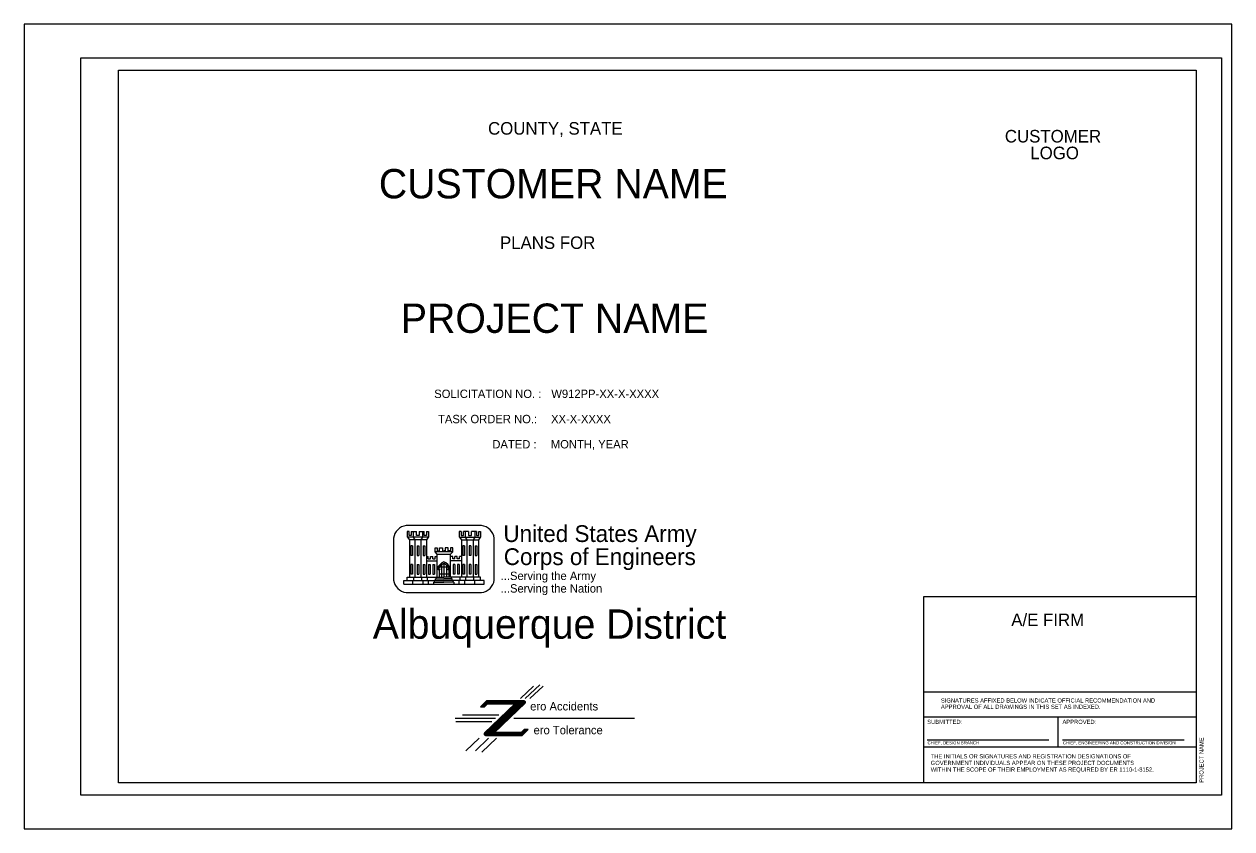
# Model space of a CAD drawing. Extents: x 0 to 288, y 0 to 192.
import ezdxf

# ---------------------------------------------------------------- set-up
doc = ezdxf.new("R2010")
doc.units = 0
for name, color, linetype in [('G-ANNO-SYMB', 7, 'Continuous'), ('G-ANNO-TEXT', 7, 'Continuous'), ('G-ANNO-TTBL', 7, 'Continuous')]:
    doc.layers.add(name, color=color, linetype=linetype)

msp = doc.modelspace()

# ---------------------------------------------------------------- linework, layer by layer
at = {"layer": 'G-ANNO-SYMB'}
for p, q in [((109.09, 72.37), (91.09, 72.37)), ((88.09, 69.37), (88.09, 59.37)), ((112.09, 59.37), (112.09, 69.37)), ((98.94, 61.94), (98.94, 61.94)), ((90.51, 59.27), (91.32, 59.27)), ((91.32, 60.08), (91.86, 60.08)), ((108.86, 60.08), (108.32, 60.08)), ((109.67, 59.27), (108.86, 59.27)), ((91.09, 56.37), (109.09, 56.37)), ((121.47, 34.07), (118.35, 31.08)), ((122.95, 34.4), (119.48, 31.08)), ((123.73, 34.07), (120.61, 31.08)), ((110.28, 30.56), (108.8, 29.15)), ((108.8, 29.15), (109.76, 29.15)), ((108.86, 29.2), (109.82, 29.2)), ((108.95, 29.28), (109.91, 29.28)), ((109.02, 29.36), (109.98, 29.36)), ((109.1, 29.43), (110.06, 29.43)), ((109.19, 29.51), (110.15, 29.51)), ((109.26, 29.59), (110.22, 29.59)), ((109.35, 29.66), (110.3, 29.66)), ((109.43, 29.74), (110.39, 29.74)), ((109.5, 29.82), (110.46, 29.82)), ((109.59, 29.89), (119.37, 29.89)), ((109.67, 29.97), (119.45, 29.97)), ((109.74, 30.05), (119.5, 30.05)), ((109.76, 29.15), (110.48, 29.84)), ((117.05, 29.84), (109.77, 22.89)), ((109.83, 30.12), (119.54, 30.12)), ((109.91, 30.2), (119.54, 30.2)), ((109.99, 30.28), (119.55, 30.28)), ((110.07, 30.36), (119.52, 30.36)), ((110.15, 30.43), (119.48, 30.43)), ((110.23, 30.51), (119.39, 30.51)), ((119.22, 30.56), (110.28, 30.56)), ((110.48, 29.84), (117.05, 29.84)), ((112.18, 23.03), (119.46, 29.98)), ((115.98, 28.82), (118.24, 28.82)), ((116.06, 28.9), (118.32, 28.9)), ((116.15, 28.97), (118.4, 28.97)), ((116.22, 29.05), (118.48, 29.05)), ((116.31, 29.13), (118.56, 29.13)), ((116.39, 29.2), (118.64, 29.2)), ((116.46, 29.28), (118.73, 29.28)), ((116.55, 29.36), (118.8, 29.36)), ((116.63, 29.43), (118.88, 29.43)), ((116.7, 29.51), (118.97, 29.51)), ((116.79, 29.59), (119.04, 29.59)), ((116.87, 29.66), (119.12, 29.66)), ((116.95, 29.74), (119.21, 29.74)), ((117.03, 29.82), (119.28, 29.82)), ((119.22, 30.56), (119.22, 30.56)), ((112.38, 26.36), (102.78, 26.36)), ((113.21, 27.15), (104.57, 27.15)), ((113.01, 25.98), (115.26, 25.98)), ((113.08, 26.05), (115.35, 26.05)), ((113.17, 26.13), (115.43, 26.13)), ((113.25, 26.21), (115.51, 26.21)), ((113.33, 26.28), (115.59, 26.28)), ((113.41, 26.36), (115.67, 26.36)), ((113.49, 26.44), (115.75, 26.44)), ((113.57, 26.52), (115.83, 26.52)), ((113.65, 26.59), (115.91, 26.59)), ((113.74, 26.67), (115.99, 26.67)), ((113.81, 26.75), (116.07, 26.75)), ((113.89, 26.82), (116.15, 26.82)), ((113.98, 26.9), (116.23, 26.9)), ((114.05, 26.98), (116.31, 26.98)), ((114.13, 27.05), (116.39, 27.05)), ((114.22, 27.13), (116.47, 27.13)), ((114.29, 27.21), (116.55, 27.21)), ((114.38, 27.28), (116.63, 27.28)), ((114.46, 27.36), (116.71, 27.36)), ((114.53, 27.44), (116.8, 27.44)), ((114.62, 27.51), (116.87, 27.51)), ((114.7, 27.59), (116.95, 27.59)), ((114.77, 27.67), (117.04, 27.67)), ((114.86, 27.74), (117.11, 27.74)), ((114.94, 27.82), (117.19, 27.82)), ((115.02, 27.9), (117.28, 27.9)), ((115.1, 27.97), (117.35, 27.97)), ((115.18, 28.05), (117.44, 28.05)), ((115.26, 28.13), (117.52, 28.13)), ((115.34, 28.2), (117.59, 28.2)), ((115.42, 28.28), (117.68, 28.28)), ((115.5, 28.36), (117.76, 28.36)), ((115.58, 28.44), (117.83, 28.44)), ((115.67, 28.51), (117.92, 28.51)), ((115.74, 28.59), (118, 28.59)), ((115.82, 28.67), (118.08, 28.67)), ((115.91, 28.74), (118.16, 28.74)), ((116.76, 26.41), (145.56, 26.41)), ((111.56, 25.57), (102.92, 25.57)), ((109.95, 23.06), (112.21, 23.06)), ((110.03, 23.14), (112.3, 23.14)), ((110.12, 23.21), (112.37, 23.21)), ((110.19, 23.29), (112.45, 23.29)), ((110.27, 23.37), (112.54, 23.37)), ((110.36, 23.44), (112.61, 23.44)), ((110.43, 23.52), (112.69, 23.52)), ((110.51, 23.6), (112.78, 23.6)), ((110.6, 23.67), (112.85, 23.67)), ((110.67, 23.75), (112.94, 23.75)), ((110.76, 23.83), (113.02, 23.83)), ((110.84, 23.9), (113.09, 23.9)), ((110.91, 23.98), (113.18, 23.98)), ((111, 24.06), (113.26, 24.06)), ((111.08, 24.13), (113.33, 24.13)), ((111.15, 24.21), (113.42, 24.21)), ((111.24, 24.29), (113.5, 24.29)), ((111.32, 24.36), (113.58, 24.36)), ((111.4, 24.44), (113.66, 24.44)), ((111.48, 24.52), (113.74, 24.52)), ((111.56, 24.6), (113.82, 24.6)), ((111.64, 24.67), (113.9, 24.67)), ((111.72, 24.75), (113.98, 24.75)), ((111.8, 24.83), (114.06, 24.83)), ((111.88, 24.9), (114.14, 24.9)), ((111.96, 24.98), (114.23, 24.98)), ((112.05, 25.06), (114.3, 25.06)), ((112.12, 25.13), (114.38, 25.13)), ((112.2, 25.21), (114.47, 25.21)), ((112.29, 25.29), (114.54, 25.29)), ((112.36, 25.36), (114.62, 25.36)), ((112.44, 25.44), (114.71, 25.44)), ((112.53, 25.52), (114.78, 25.52)), ((112.6, 25.59), (114.87, 25.59)), ((112.69, 25.67), (114.95, 25.67)), ((112.77, 25.75), (115.02, 25.75)), ((112.84, 25.82), (115.11, 25.82)), ((112.93, 25.9), (115.19, 25.9)), ((119.27, 23.72), (118.55, 23.03)), ((118.58, 23.06), (119.54, 23.06)), ((118.66, 23.14), (119.62, 23.14)), ((118.75, 23.21), (119.7, 23.21)), ((118.76, 22.31), (120.23, 23.72)), ((118.82, 23.29), (119.78, 23.29)), ((118.9, 23.37), (119.86, 23.37)), ((118.99, 23.44), (119.95, 23.44)), ((119.06, 23.52), (120.02, 23.52)), ((119.14, 23.6), (120.1, 23.6)), ((119.23, 23.67), (120.19, 23.67)), ((120.23, 23.72), (119.27, 23.72)), ((108.47, 21.64), (105.35, 18.65)), ((107.6, 18.65), (110.72, 21.64)), ((112.63, 21.64), (109.15, 18.33)), ((109.67, 22.6), (119.05, 22.6)), ((109.68, 22.75), (119.22, 22.75)), ((109.68, 22.68), (119.14, 22.68)), ((109.7, 22.52), (118.98, 22.52)), ((109.73, 22.83), (119.3, 22.83)), ((109.74, 22.44), (118.9, 22.44)), ((109.79, 22.91), (119.38, 22.91)), ((109.83, 22.37), (118.81, 22.37)), ((109.87, 22.98), (119.46, 22.98)), ((110.01, 22.31), (118.76, 22.31)), ((118.55, 23.03), (112.18, 23.03))]:
    msp.add_line(p, q, dxfattribs=at)
for points in [[(91.79, 70.94), (91.32, 70.94), (91.32, 69.65), (91.86, 68.97), (91.86, 60.08)], [(96.41, 69.59), (91.37, 69.59)], [(92.33, 70.94), (92.33, 69.99), (91.79, 69.99), (91.79, 70.94)], [(92.33, 70.94), (93.55, 70.94)], [(92.74, 70.94), (92.74, 69.61), (93.14, 68.94), (93.14, 60.08)], [(94.22, 70.94), (94.22, 69.99), (93.55, 69.99), (93.55, 70.94)], [(94.22, 70.94), (95.43, 70.94)], [(95.03, 70.94), (95.03, 69.61), (94.63, 68.94), (94.63, 60.08)], [(95.98, 70.94), (95.98, 69.99), (95.43, 69.99), (95.43, 70.94)], [(95.98, 70.94), (96.45, 70.94), (96.45, 69.65), (95.91, 68.97), (95.91, 60.08)], [(104.21, 70.94), (103.74, 70.94), (103.74, 69.65), (104.27, 68.97), (104.27, 60.08)], [(103.78, 69.59), (108.82, 69.59)], [(104.21, 70.94), (104.21, 69.99), (104.75, 69.99), (104.75, 70.94)], [(105.96, 70.94), (104.75, 70.94)], [(105.15, 70.94), (105.15, 69.61), (105.56, 68.94), (105.56, 60.08)], [(105.96, 70.94), (105.96, 69.99), (106.64, 69.99), (106.64, 70.94)], [(107.85, 70.94), (106.64, 70.94)], [(107.45, 70.94), (107.45, 69.61), (107.04, 68.94), (107.04, 60.08)], [(107.85, 70.94), (107.85, 69.99), (108.39, 69.99), (108.39, 70.94)], [(108.39, 70.94), (108.86, 70.94), (108.86, 69.65), (108.32, 68.97), (108.32, 60.08)], [(95.92, 68.98), (91.85, 68.98)], [(92.6, 67.5), (92.2, 67.5)], [(92.2, 67.5), (92.2, 65.21)], [(92.6, 67.5), (92.6, 65.21)], [(93.69, 67.5), (94.09, 67.5)], [(93.69, 67.5), (93.69, 65.21)], [(94.09, 67.5), (94.09, 65.21)], [(95.17, 67.5), (95.17, 65.21)], [(95.17, 67.5), (95.57, 67.5)], [(95.57, 67.5), (95.57, 65.21)], [(98.47, 60.08), (98.47, 65.55), (98, 66.08), (98, 67.03), (98.47, 67.03)], [(98.47, 67.03), (98.47, 66.35), (99.08, 66.35), (99.08, 67.03)], [(99.08, 67.03), (99.76, 67.03)], [(99.76, 67.03), (99.76, 66.35), (100.16, 66.35)], [(100.43, 67.03), (100.43, 66.35), (100.16, 66.35)], [(101.1, 67.03), (100.43, 67.03)], [(101.71, 67.03), (101.71, 66.35), (101.1, 66.35), (101.1, 67.03)], [(101.71, 60.08), (101.71, 65.55), (102.19, 66.08), (102.19, 67.03), (101.71, 67.03)], [(104.27, 68.98), (108.33, 68.98)], [(105.01, 67.5), (104.61, 67.5)], [(104.61, 67.5), (104.61, 65.21)], [(105.01, 67.5), (105.01, 65.21)], [(106.09, 67.5), (106.09, 65.21)], [(106.49, 67.5), (106.09, 67.5)], [(106.49, 67.5), (106.49, 65.21)], [(107.58, 67.5), (107.58, 65.21)], [(107.58, 67.5), (107.98, 67.5)], [(107.98, 67.5), (107.98, 65.21)], [(92.6, 65.21), (92.2, 65.21)], [(93.69, 65.21), (94.09, 65.21)], [(95.17, 65.21), (95.57, 65.21)], [(95.91, 65), (96.38, 65)], [(95.91, 63.92), (98.47, 63.92)], [(96.38, 64.46), (96.38, 65)], [(96.38, 64.46), (96.92, 64.46)], [(96.92, 65), (97.46, 65)], [(96.92, 64.46), (96.92, 65)], [(97.46, 64.46), (97.46, 65)], [(97.46, 64.46), (98, 64.46)], [(98, 65), (98.47, 65)], [(98, 64.46), (98, 65)], [(102.19, 66.08), (98.01, 66.08)], [(98.47, 65.55), (101.67, 65.55)], [(102.19, 65), (101.71, 65)], [(104.27, 63.92), (101.71, 63.92)], [(102.19, 64.46), (102.19, 65)], [(102.73, 64.46), (102.19, 64.46)], [(102.73, 64.46), (102.73, 65)], [(103.26, 65), (102.73, 65)], [(103.26, 64.46), (103.26, 65)], [(103.8, 64.46), (103.26, 64.46)], [(103.8, 64.46), (103.8, 65)], [(104.27, 65), (103.8, 65)], [(105.01, 65.21), (104.61, 65.21)], [(106.49, 65.21), (106.09, 65.21)], [(107.58, 65.21), (107.98, 65.21)], [(92.6, 63.05), (92.2, 63.05)], [(92.2, 63.05), (92.2, 60.75)], [(92.6, 60.75), (92.2, 60.75)], [(92.6, 63.05), (92.6, 60.75)], [(93.69, 63.05), (94.09, 63.05)], [(93.69, 63.05), (93.69, 60.75)], [(93.69, 60.75), (94.09, 60.75)], [(94.09, 63.05), (94.09, 60.75)], [(95.17, 63.05), (95.17, 60.75)], [(95.17, 63.05), (95.57, 63.05)], [(95.17, 60.75), (95.57, 60.75)], [(95.57, 63.05), (95.57, 60.75)], [(96.42, 63.05), (96.83, 63.05)], [(96.42, 63.05), (96.42, 60.75)], [(96.42, 60.75), (96.83, 60.75)], [(96.83, 63.05), (96.83, 60.75)], [(97.45, 63.05), (97.45, 60.75)], [(97.45, 63.05), (97.86, 63.05)], [(97.45, 60.75), (97.86, 60.75)], [(97.86, 63.05), (97.86, 60.75)], [(98.94, 61.94), (98.47, 61.94)], [(98.93, 61.85), (98.93, 60.09)], [(101.25, 60.79), (98.93, 60.79)], [(101.15, 62.45), (99.04, 62.45)], [(99.49, 62.9), (99.49, 60.09)], [(100.09, 63.31), (100.09, 60.09)], [(100.69, 62.9), (100.69, 60.09)], [(101.24, 61.94), (101.71, 61.94)], [(101.25, 61.85), (101.25, 60.09)], [(102.74, 63.05), (102.33, 63.05)], [(102.33, 63.05), (102.33, 60.75)], [(102.74, 60.75), (102.33, 60.75)], [(102.74, 63.05), (102.74, 60.75)], [(103.36, 63.05), (103.36, 60.75)], [(103.77, 63.05), (103.36, 63.05)], [(103.77, 60.75), (103.36, 60.75)], [(103.77, 63.05), (103.77, 60.75)], [(105.01, 63.05), (104.61, 63.05)], [(104.61, 63.05), (104.61, 60.75)], [(105.01, 60.75), (104.61, 60.75)], [(105.01, 63.05), (105.01, 60.75)], [(106.09, 63.05), (106.09, 60.75)], [(106.49, 63.05), (106.09, 63.05)], [(106.49, 60.75), (106.09, 60.75)], [(106.49, 63.05), (106.49, 60.75)], [(107.58, 63.05), (107.58, 60.75)], [(107.58, 63.05), (107.98, 63.05)], [(107.58, 60.75), (107.98, 60.75)], [(107.98, 63.05), (107.98, 60.75)], [(90.51, 59.27), (100.09, 59.27)], [(90.51, 58.39), (90.51, 59.27)], [(90.51, 58.39), (109.67, 58.39)], [(91.32, 59.27), (91.32, 60.08)], [(91.86, 60.08), (100.09, 60.08)], [(92.67, 58.39), (92.67, 59.27)], [(92.94, 59.27), (92.94, 60.08)], [(94.84, 59.27), (94.84, 60.08)], [(95.12, 58.39), (95.12, 59.27)], [(96.19, 59.27), (96.19, 60.08)], [(96.46, 58.39), (96.46, 59.27)], [(97.67, 58.39), (97.67, 58.85)], [(97.67, 58.85), (100.09, 58.85)], [(97.84, 58.85), (97.84, 59.27)], [(98.11, 59.66), (100.09, 59.66)], [(98.11, 59.27), (98.11, 59.66)], [(98.29, 59.66), (98.29, 60.08)], [(108.86, 60.08), (100.09, 60.08)], [(102.07, 59.66), (100.09, 59.66)], [(109.67, 59.27), (100.09, 59.27)], [(102.48, 58.85), (100.09, 58.85)], [(101.89, 59.66), (101.89, 60.08)], [(102.07, 59.27), (102.07, 59.66)], [(102.34, 58.85), (102.34, 59.27)], [(102.51, 58.39), (102.51, 58.85)], [(103.72, 58.39), (103.72, 59.27)], [(103.99, 59.27), (103.99, 60.08)], [(105.07, 58.39), (105.07, 59.27)], [(105.34, 59.27), (105.34, 60.08)], [(107.24, 59.27), (107.24, 60.08)], [(107.51, 58.39), (107.51, 59.27)], [(108.86, 59.27), (108.86, 60.08)], [(109.67, 58.39), (109.67, 59.27)]]:
    msp.add_lwpolyline(points, dxfattribs=at)
for centre in [(98.94, 61.95), (101.25, 61.95)]:
    msp.add_circle(centre, 0.202, dxfattribs=at)
for centre, radius, start, end in [((91.59, 68.87), 3.54, 98.1301, 171.8699), ((108.59, 68.87), 3.54, 8.1301, 81.8699), ((101.86, 60.23), 3.93, 116.7422, 149.566), ((98.32, 60.23), 3.93, 30.434, 63.2578), ((101.36, 60.69), 2.91, 115.7012, 153.9247), ((98.83, 60.71), 2.9, 25.7994, 64.0175), ((91.59, 59.87), 3.54, 188.1301, 261.8699), ((108.59, 59.87), 3.54, 278.1301, 351.8699), ((119.22, 30.22), 0.336, 313.6028, 90), ((110.01, 22.65), 0.336, 133.593, 270)]:
    msp.add_arc(centre, radius, start, end, dxfattribs=at)
at = {"layer": 'G-ANNO-TEXT'}
for p, q in [((246.54, 26.71), (246.54, 19.61)), ((215.33, 21.28), (244.35, 21.28)), ((247.61, 21.28), (276.63, 21.28))]:
    msp.add_line(p, q, dxfattribs=at)
at = {"layer": 'G-ANNO-TTBL'}
for p, q in [((214.56, 32.66), (279.5, 32.66)), ((214.39, 26.71), (279.5, 26.71)), ((214.56, 19.61), (279.5, 19.61))]:
    msp.add_line(p, q, dxfattribs=at)
for points in [[(288, 192), (0, 192), (0, 0), (288, 0)], [(13.5, 184), (285.5, 184), (285.5, 8), (13.5, 8)], [(22.5, 181), (279.5, 181), (279.5, 11), (22.5, 11)], [(214.56, 55.42), (279.5, 55.42), (279.5, 11), (214.56, 11)]]:
    msp.add_lwpolyline(points, close=True, dxfattribs=at)

# ---------------------------------------------------------------- texts
at = {"layer": 'G-ANNO-SYMB'}
for s, height, p in [('United States Army', 4, (114.29, 68.44)), ('Corps of Engineers', 4, (114.38, 62.94)), ('...Serving the Army', 2, (113.63, 59.37)), ('...Serving the Nation', 2, (113.63, 56.37)), ('ero Accidents', 2, (120.67, 28.25)), ('ero Tolerance', 2, (121.48, 22.57))]:
    msp.add_text(s, height=height, dxfattribs=at).set_placement(p)
at = {"layer": 'G-ANNO-TEXT'}
for s, height, p in [('COUNTY, STATE', 3, (110.63, 165.63)), ('CUSTOMER', 3, (233.87, 163.76)), ('LOGO', 3, (239.94, 159.77)), ('CUSTOMER NAME', 7, (84.58, 150.43)), ('PLANS FOR', 3, (113.47, 138.36)), ('PROJECT NAME', 7, (89.83, 118.34)), ('SOLICITATION NO. :', 2, (97.79, 102.8)), ('W912PP-XX-X-XXXX', 2, (125.71, 102.8)), ('TASK ORDER NO.:', 2, (98.7, 96.78)), ('XX-X-XXXX', 2, (125.65, 96.78)), ('DATED :', 2, (111.65, 90.76)), ('MONTH, YEAR', 2, (125.6, 90.77)), ('Albuquerque District', 7, (83.13, 45.37)), ('A/E FIRM', 3, (235.4, 48.38))]:
    msp.add_text(s, height=height, dxfattribs=at).set_placement(p)
msp.add_text('PROJECT NAME', height=1, rotation=90, dxfattribs=at).set_placement((281.25, 11))
at = {"layer": 'G-ANNO-TTBL'}
for s, height, p in [('APPROVAL OF ALL DRAWINGS IN THIS SET AS INDEXED.', 1, (218.62, 28.63)), ('SIGNATURES AFFIXED BELOW INDICATE OFFICIAL RECOMMENDATION AND', 1, (218.62, 30.13)), ('SUBMITTED:', 1, (215.35, 25.03)), ('APPROVED:', 1, (247.61, 25.03)), ('CHIEF, DESIGN BRANCH', 0.75, (215.43, 20.16)), ('CHIEF, ENGINEERING AND CONSTRUCTION DIVISION', 0.75, (247.7, 20.16)), ('THE INITIALS OR SIGNATURES AND REGISTRATION DESIGNATIONS OF', 1, (216.2, 16.82)), ('WITHIN THE SCOPE OF THEIR EMPLOYMENT AS REQUIRED BY ER 1110-1-8152.', 1, (216.2, 13.65)), ('GOVERNMENT INDIVIDUALS APPEAR ON THESE PROJECT DOCUMENTS', 1, (216.2, 15.24))]:
    msp.add_text(s, height=height, dxfattribs=at).set_placement(p)

doc.saveas('drawing.dxf')
